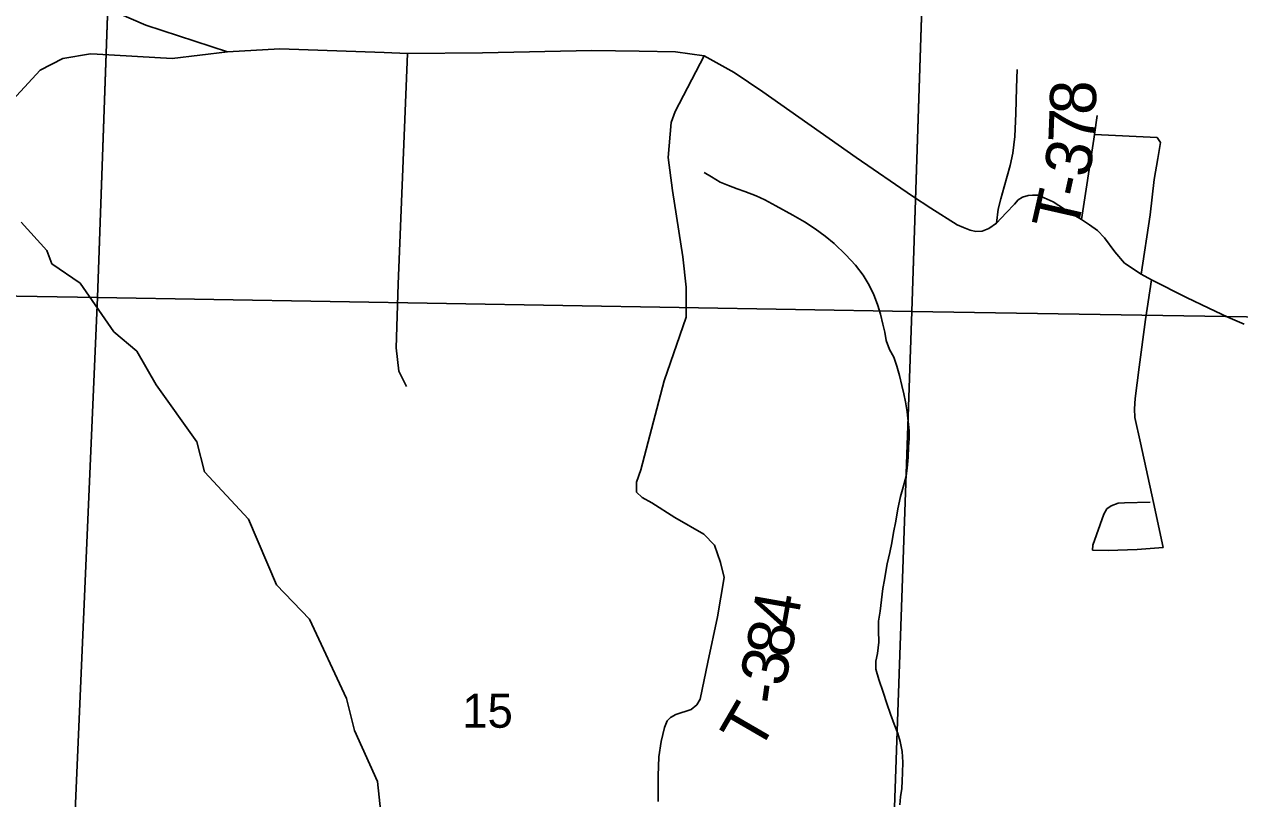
# Model space of a CAD drawing. Extents: x 2.1 to 8.9, y 14.1 to 20.9.
# Drawn here: x 3.368 to 4.863, y 15.488 to 16.441 of the extents above; entities that cross this region are included whole.
import ezdxf

# ---------------------------------------------------------------- set-up
doc = ezdxf.new("R2010")
doc.units = 0
for name, color, linetype in [('GM_X_City_Street', 7, 'Continuous'), ('GM_X_County_Road_Text', 7, 'Continuous'), ('GM_X_Interchange_Ramps', 7, 'Continuous'), ('GM_X_Minor_River_Text', 7, 'Continuous'), ('GM_X_State_Shield', 7, 'Continuous'), ('TX_P_Misc', 7, 'Continuous')]:
    doc.layers.add(name, color=color, linetype=linetype)

msp = doc.modelspace()

# ---------------------------------------------------------------- linework, layer by layer
at = {"layer": 'GM_X_City_Street'}
for p, q in [((3.517, 16.4401), (3.4685, 16.4612)), ((3.6176, 16.4072), (3.517, 16.4401)), ((3.8274, 16.1216), (3.8391, 16.4054)), ((4.1683, 16.3338), (4.204, 16.4026)), ((4.5879, 16.3629), (4.5888, 16.3855)), ((4.5871, 16.3315), (4.5879, 16.3629)), ((4.1634, 16.3203), (4.1683, 16.3338)), ((4.5859, 16.3032), (4.5871, 16.3315)), ((4.6842, 16.3056), (4.6871, 16.3292)), ((4.1597, 16.2772), (4.1634, 16.3203)), ((4.5834, 16.2827), (4.5859, 16.3032)), ((4.6682, 16.2012), (4.6833, 16.2997)), ((4.6833, 16.2997), (4.6842, 16.3056)), ((4.6842, 16.3056), (4.761, 16.3019)), ((4.765, 16.2957), (4.761, 16.3019)), ((4.5802, 16.2675), (4.5834, 16.2827)), ((4.7621, 16.2759), (4.765, 16.2957)), ((4.1649, 16.2367), (4.1597, 16.2772)), ((4.5728, 16.2411), (4.5802, 16.2675)), ((4.7572, 16.2503), (4.7621, 16.2759)), ((4.1776, 16.1551), (4.1649, 16.2367)), ((4.5686, 16.2264), (4.5728, 16.2411)), ((4.7526, 16.207), (4.7572, 16.2503)), ((4.5654, 16.2136), (4.5686, 16.2264)), ((4.5636, 16.1967), (4.5654, 16.2136)), ((4.7412, 16.1337), (4.7526, 16.207)), ((4.1818, 16.118), (4.1776, 16.1551)), ((3.8248, 16.0431), (3.8274, 16.1216)), ((4.1818, 16.0809), (4.1818, 16.118)), ((4.7466, 16.0782), (4.7541, 16.127)), ((4.1548, 16.0027), (4.1818, 16.0809)), ((4.739, 16.0194), (4.7466, 16.0782)), ((3.8281, 16.0146), (3.8248, 16.0431)), ((3.8378, 15.9958), (3.8281, 16.0146)), ((4.7342, 15.981), (4.739, 16.0194)), ((4.126, 15.8931), (4.1548, 16.0027)), ((4.733, 15.9683), (4.7342, 15.981)), ((4.7335, 15.9573), (4.733, 15.9683)), ((4.7405, 15.9263), (4.7335, 15.9573)), ((4.7565, 15.8529), (4.7405, 15.9263)), ((4.1208, 15.878), (4.126, 15.8931)), ((4.1207, 15.8742), (4.1208, 15.878)), ((4.1205, 15.8655), (4.1207, 15.8742)), ((4.1274, 15.8589), (4.1205, 15.8655)), ((4.1394, 15.8524), (4.1274, 15.8589)), ((4.1678, 15.8343), (4.1394, 15.8524)), ((4.7044, 15.8488), (4.6992, 15.8451)), ((4.713, 15.852), (4.7044, 15.8488)), ((4.7208, 15.8524), (4.713, 15.852)), ((4.7526, 15.8532), (4.7208, 15.8524)), ((4.7684, 15.7974), (4.7565, 15.8529)), ((4.2036, 15.8141), (4.1678, 15.8343)), ((4.6954, 15.8386), (4.6819, 15.8006)), ((4.6992, 15.8451), (4.6954, 15.8386)), ((4.2167, 15.8005), (4.2036, 15.8141)), ((4.224, 15.7792), (4.2167, 15.8005)), ((4.6819, 15.8006), (4.6814, 15.7942)), ((4.6814, 15.7942), (4.701, 15.794)), ((4.701, 15.794), (4.7363, 15.795)), ((4.7363, 15.795), (4.7684, 15.7974)), ((4.2284, 15.7606), (4.224, 15.7792)), ((4.2201, 15.7121), (4.2284, 15.7606)), ((4.2084, 15.6563), (4.2201, 15.7121)), ((4.1989, 15.6109), (4.2084, 15.6563)), ((4.195, 15.6041), (4.1989, 15.6109)), ((4.169, 15.5921), (4.188, 15.5982)), ((4.188, 15.5982), (4.195, 15.6041)), ((4.1552, 15.576), (4.1582, 15.5842)), ((4.1582, 15.5842), (4.1626, 15.5883)), ((4.1626, 15.5883), (4.169, 15.5921)), ((4.1511, 15.559), (4.1552, 15.576)), ((4.148, 15.54), (4.1511, 15.559)), ((4.1472, 15.5165), (4.148, 15.54)), ((4.1473, 15.4852), (4.1472, 15.5165))]:
    msp.add_line(p, q, dxfattribs=at)
at = {"layer": 'GM_X_Interchange_Ramps'}
for p, q in [((3.4934, 17.1171), (3.4577, 16.1051)), ((3.4577, 16.1051), (3.4934, 17.1171)), ((4.4928, 17.1099), (4.4591, 16.088)), ((4.4591, 16.088), (4.4928, 17.1099)), ((3.4577, 16.1051), (2.4631, 16.1204)), ((2.4631, 16.1204), (3.4577, 16.1051)), ((3.4577, 16.1051), (3.4148, 15.1232)), ((3.4148, 15.1232), (3.4577, 16.1051)), ((4.4591, 16.088), (3.4577, 16.1051)), ((3.4577, 16.1051), (4.4591, 16.088)), ((4.4591, 16.088), (4.4256, 15.1132)), ((4.4256, 15.1132), (4.4591, 16.088)), ((5.4597, 16.0717), (4.4591, 16.088)), ((4.4591, 16.088), (5.4597, 16.0717))]:
    msp.add_line(p, q, dxfattribs=at)
at = {"layer": 'GM_X_State_Shield'}
for p, q in [((3.4149, 16.3993), (3.4489, 16.405)), ((3.4489, 16.405), (3.457, 16.4045)), ((3.457, 16.4045), (3.5495, 16.3993)), ((3.5495, 16.3993), (3.6176, 16.4072)), ((3.6176, 16.4072), (3.682, 16.4109)), ((3.682, 16.4109), (3.8102, 16.4064)), ((3.8102, 16.4064), (3.8391, 16.4054)), ((3.8391, 16.4054), (3.9312, 16.4062)), ((3.9312, 16.4062), (4.0658, 16.4089)), ((4.0658, 16.4089), (4.1237, 16.4082)), ((4.1237, 16.4082), (4.1687, 16.4072)), ((4.1687, 16.4072), (4.204, 16.4026)), ((4.204, 16.4026), (4.2406, 16.3821)), ((3.387, 16.3849), (3.4149, 16.3993)), ((3.1953, 16.1767), (3.387, 16.3849)), ((4.2406, 16.3821), (4.276, 16.358)), ((4.276, 16.358), (4.3909, 16.2772)), ((4.3909, 16.2772), (4.4602, 16.2296)), ((4.4602, 16.2296), (4.4825, 16.215)), ((4.5855, 16.2201), (4.5901, 16.2253)), ((4.5901, 16.2253), (4.5956, 16.2287)), ((4.5956, 16.2287), (4.6022, 16.2306)), ((4.6022, 16.2306), (4.6076, 16.2311)), ((4.6076, 16.2311), (4.6145, 16.2308)), ((4.6145, 16.2308), (4.6222, 16.2278)), ((4.6222, 16.2278), (4.6331, 16.2228)), ((4.6331, 16.2228), (4.6403, 16.2184)), ((4.4825, 16.215), (4.5149, 16.1947)), ((4.5636, 16.1967), (4.5752, 16.2091)), ((4.5752, 16.2091), (4.5855, 16.2201)), ((4.6403, 16.2184), (4.6539, 16.2093)), ((4.6539, 16.2093), (4.6682, 16.2012)), ((4.5149, 16.1947), (4.5227, 16.1911)), ((4.5541, 16.19), (4.5636, 16.1967)), ((4.6682, 16.2012), (4.6778, 16.1943)), ((4.6778, 16.1943), (4.6875, 16.1877)), ((4.5227, 16.1911), (4.5309, 16.1878)), ((4.5309, 16.1878), (4.5379, 16.1864)), ((4.5379, 16.1864), (4.5459, 16.1869)), ((4.5459, 16.1869), (4.5541, 16.19)), ((4.6875, 16.1877), (4.6962, 16.1783)), ((4.6962, 16.1783), (4.7092, 16.1614)), ((4.7092, 16.1614), (4.721, 16.1473)), ((4.721, 16.1473), (4.7412, 16.1337)), ((4.7412, 16.1337), (4.7541, 16.127)), ((4.7541, 16.127), (4.7972, 16.1051)), ((4.7972, 16.1051), (4.8247, 16.0918)), ((4.8247, 16.0918), (4.8482, 16.0809)), ((4.8482, 16.0809), (4.8683, 16.0722))]:
    msp.add_line(p, q, dxfattribs=at)
at = {"layer": 'TX_P_Misc'}
for p, q in [((4.2127, 16.2536), (4.2038, 16.259)), ((4.2236, 16.2471), (4.2127, 16.2536)), ((4.2336, 16.2428), (4.2236, 16.2471)), ((4.2444, 16.2386), (4.2336, 16.2428)), ((4.254, 16.2355), (4.2444, 16.2386)), ((4.2678, 16.2302), (4.254, 16.2355)), ((4.2786, 16.2252), (4.2678, 16.2302)), ((4.2921, 16.218), (4.2786, 16.2252)), ((4.313, 16.2065), (4.2921, 16.218)), ((4.3273, 16.1982), (4.313, 16.2065)), ((3.3954, 16.1631), (3.3638, 16.1979)), ((4.3405, 16.1894), (4.3273, 16.1982)), ((4.3526, 16.1807), (4.3405, 16.1894)), ((4.3639, 16.1715), (4.3526, 16.1807)), ((3.4014, 16.1464), (3.3954, 16.1631)), ((4.378, 16.1575), (4.3639, 16.1715)), ((3.4362, 16.1227), (3.4014, 16.1464)), ((4.3902, 16.1449), (4.378, 16.1575)), ((4.3993, 16.1327), (4.3902, 16.1449)), ((4.4057, 16.1222), (4.3993, 16.1327)), ((3.4777, 16.0629), (3.4362, 16.1227)), ((4.4122, 16.1095), (4.4057, 16.1222)), ((4.4176, 16.0952), (4.4122, 16.1095)), ((4.4206, 16.0846), (4.4176, 16.0952)), ((4.4236, 16.0721), (4.4206, 16.0846)), ((4.4262, 16.0623), (4.4236, 16.0721)), ((3.5061, 16.039), (3.4777, 16.0629)), ((4.4277, 16.0521), (4.4262, 16.0623)), ((4.4318, 16.0412), (4.4277, 16.0521)), ((3.5299, 15.9976), (3.5061, 16.039)), ((4.4371, 16.0315), (4.4318, 16.0412)), ((4.4408, 16.0206), (4.4371, 16.0315)), ((4.4442, 16.0092), (4.4408, 16.0206)), ((3.5799, 15.9277), (3.5299, 15.9976)), ((4.4469, 15.9968), (4.4442, 16.0092)), ((4.4495, 15.9866), (4.4469, 15.9968)), ((4.4517, 15.9767), (4.4495, 15.9866)), ((4.4536, 15.9643), (4.4517, 15.9767)), ((4.4562, 15.9411), (4.4536, 15.9643)), ((4.4561, 15.9316), (4.4562, 15.9411)), ((3.5892, 15.8905), (3.5799, 15.9277)), ((4.4553, 15.9213), (4.4561, 15.9316)), ((4.4535, 15.895), (4.4546, 15.9087)), ((4.4546, 15.9087), (4.4553, 15.9213)), ((4.4522, 15.8851), (4.4535, 15.895)), ((3.6435, 15.8325), (3.5892, 15.8905)), ((4.4485, 15.8716), (4.4522, 15.8851)), ((4.4454, 15.8601), (4.4485, 15.8716)), ((4.4421, 15.8452), (4.4454, 15.8601)), ((3.6778, 15.7517), (3.6435, 15.8325)), ((4.4395, 15.8299), (4.4421, 15.8452)), ((4.4369, 15.8161), (4.4395, 15.8299)), ((4.4324, 15.7912), (4.4347, 15.8031)), ((4.4347, 15.8031), (4.4369, 15.8161)), ((4.429, 15.7774), (4.4324, 15.7912)), ((4.4274, 15.7679), (4.429, 15.7774)), ((4.4238, 15.7472), (4.4258, 15.7579)), ((4.4258, 15.7579), (4.4274, 15.7679)), ((3.7183, 15.7094), (3.6778, 15.7517)), ((4.422, 15.7331), (4.4238, 15.7472)), ((4.4202, 15.7193), (4.422, 15.7331)), ((4.4183, 15.7067), (4.4202, 15.7193)), ((3.7638, 15.6116), (3.7183, 15.7094)), ((4.4182, 15.6953), (4.4183, 15.7067)), ((4.4187, 15.6812), (4.4182, 15.6953)), ((4.4172, 15.6671), (4.4187, 15.6812)), ((4.4149, 15.6575), (4.4172, 15.6671)), ((4.4151, 15.648), (4.4149, 15.6575)), ((4.4186, 15.6352), (4.4151, 15.648)), ((4.424, 15.6194), (4.4186, 15.6352)), ((3.7736, 15.5723), (3.7638, 15.6116)), ((4.4286, 15.6055), (4.424, 15.6194)), ((4.4329, 15.5923), (4.4286, 15.6055)), ((4.4374, 15.5803), (4.4329, 15.5923)), ((4.442, 15.5686), (4.4374, 15.5803)), ((3.8019, 15.5096), (3.7736, 15.5723)), ((4.4449, 15.5588), (4.442, 15.5686)), ((4.4476, 15.5467), (4.4449, 15.5588)), ((4.4484, 15.5334), (4.4476, 15.5467)), ((4.448, 15.5205), (4.4484, 15.5334)), ((4.4476, 15.5106), (4.448, 15.5205)), ((3.8069, 15.4633), (3.8019, 15.5096)), ((4.4471, 15.5011), (4.4476, 15.5106)), ((4.4447, 15.4808), (4.4455, 15.4907)), ((4.4455, 15.4907), (4.4471, 15.5011))]:
    msp.add_line(p, q, dxfattribs=at)

# ---------------------------------------------------------------- texts
at = {"layer": 'GM_X_County_Road_Text'}
msp.add_text('15', height=0.04186, rotation=0, dxfattribs=at).set_placement((3.9063, 15.5758))
at = {"layer": 'GM_X_Minor_River_Text'}
for s, rotation, p in [('8', 88.0149, (4.6853, 16.3292)), ('7', 87.8139, (4.6839, 16.294)), ('3', 80.2124, (4.6771, 16.2514)), ('-', 77.5076, (4.6715, 16.2257)), ('T', 77.1955, (4.662, 16.184)), ('4', 79.9925, (4.317, 15.6953)), ('8', 78.7514, (4.31, 15.6597)), ('3', 78.3461, (4.3028, 15.625)), ('-', 81.9377, (4.2997, 15.6028)), ('T', 59.8697, (4.2706, 15.5436))]:
    msp.add_text(s, height=0.0568, rotation=rotation, dxfattribs=at).set_placement(p)

doc.saveas('drawing.dxf')
